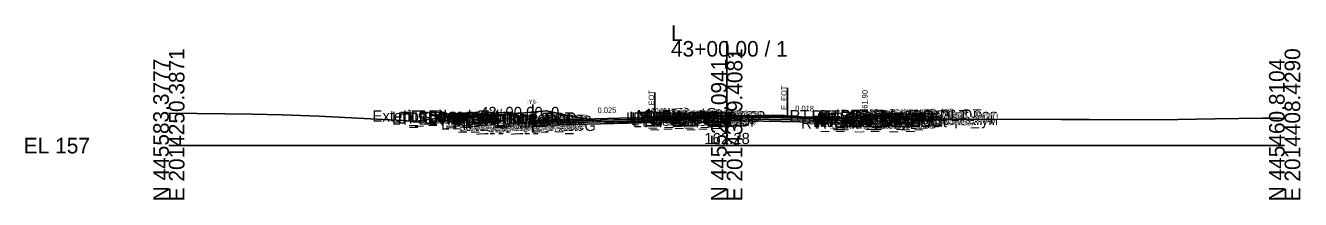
# Model space of a CAD drawing. Extents: x -26 to 4203, y -10 to 9526.
# Drawn here: x 2974.3 to 3202.8, y 2990.3 to 3021.6 of the extents above; entities that cross this region are included whole.
import ezdxf

# ---------------------------------------------------------------- set-up
doc = ezdxf.new("R2010")
doc.units = 0
for name, color, linetype in [('Default', 7, 'Continuous'), ('Exist CMT Pavement', 7, 'Continuous'), ('Exist Cross Section Cell', 7, 'Continuous'), ('Exist XS Center Line Elevation Label', 7, 'Continuous'), ('Exist XS Ground Line', 7, 'Continuous'), ('Prop CMT Conc Surface', 7, 'Continuous'), ('Prop CMT Concrete Structures', 7, 'Continuous'), ('Prop CMT Pvmt Course 1', 7, 'Continuous'), ('Prop CMT Pvmt Course 1 CG', 7, 'Continuous'), ('Prop CMT Pvmt Course 1 Wedge', 7, 'Continuous'), ('Prop CMT Pvmt Course 2', 7, 'Continuous'), ('Prop CMT Pvmt Course 2 Wedge', 7, 'Continuous'), ('Prop CMT Pvmt Course 3', 7, 'Continuous'), ('Prop CMT Pvmt Surface', 7, 'Continuous'), ('Prop CMT Pvmt Wedge Surface 1', 7, 'Continuous'), ('Prop CMT Pvmt Wedge Surface 2', 7, 'Continuous'), ('Prop CMT Pvmt Wedge Surface 3', 7, 'Continuous'), ('Prop CMT Shear Line', 7, 'Continuous'), ('Prop CMT Shear Line Text', 7, 'Continuous'), ('Prop CMT Slope Grass', 7, 'Continuous'), ('Prop CMT Subgrade Earthwork', 7, 'Continuous'), ('Prop XS Hydro Elevations', 7, 'Continuous'), ('Prop XS Label Text', 7, 'Continuous'), ('Prop XS SE Text', 7, 'Continuous'), ('Prop XS Side Slope Text', 7, 'Continuous'), ('Scratch_Level_0', 7, 'Continuous')]:
    doc.layers.add(name, color=color, linetype=linetype)

msp = doc.modelspace()

# ---------------------------------------------------------------- linework, layer by layer
at = {"layer": 'Exist CMT Pavement'}
for p, q in [((3097.81, 3005.2), (3099.49, 3005.27)), ((3099.49, 3005.27), (3100, 3005.28)), ((3087.09, 3004.57), (3088.54, 3004.67)), ((3088.54, 3004.67), (3090.65, 3004.8)), ((3090.65, 3004.8), (3092, 3004.89)), ((3092, 3004.89), (3095.19, 3005.08)), ((3095.19, 3005.08), (3096.95, 3005.16)), ((3096.95, 3005.16), (3097.81, 3005.2))]:
    msp.add_line(p, q, dxfattribs=at)
at = {"layer": 'Exist Cross Section Cell'}
for p, q in [((3100, 3000), (3100, 3018.79)), ((3000, 3000), (3100, 3000)), ((3100, 3000), (3200, 3000))]:
    msp.add_line(p, q, dxfattribs=at)
at = {"layer": 'Exist XS Ground Line'}
msp.add_lwpolyline([(3000, 3005.8), (3010.04, 3005.71), (3014.92, 3005.64), (3020.3, 3005.54), (3026.96, 3005.29), (3041.88, 3004.49), (3043.52, 3004.41), (3044.34, 3004.36), (3046.52, 3004.71), (3050.39, 3005.31), (3053.15, 3005.33), (3060.56, 3005.56), (3064.26, 3005.94), (3067.7, 3006.25), (3072.33, 3005.23), (3079.29, 3004.04), (3082.76, 3004.21), (3084.57, 3004.38), (3086.44, 3004.52), (3087.23, 3004.57), (3087.93, 3004.63), (3088.54, 3004.67), (3090.65, 3004.8), (3091.08, 3004.83), (3092.62, 3004.93), (3093.85, 3005.01), (3094.43, 3005.04), (3095.19, 3005.08), (3096.95, 3005.16), (3098.52, 3005.23), (3099.49, 3005.27), (3100.16, 3005.28), (3102.93, 3005.33), (3103.35, 3005.33), (3105.07, 3005.37), (3106.49, 3005.38), (3107.33, 3005.38), (3109.55, 3005.4), (3110.27, 3005.41), (3110.89, 3005.37), (3111.64, 3005.31), (3116.75, 3004.95), (3124.41, 3004.91), (3130.71, 3004.88), (3140.26, 3004.68), (3147.6, 3004.75), (3159.94, 3004.72), (3164.94, 3004.68), (3173.53, 3004.63), (3180.85, 3004.69), (3187.55, 3004.79), (3195.95, 3004.94), (3197.78, 3004.92), (3198.42, 3004.91), (3199, 3004.91), (3200, 3004.9)], dxfattribs=at)
at = {"layer": 'Prop CMT Conc Surface'}
for points in [[(3124.75, 3004.9), (3124.75, 3005.4), (3125.25, 3005.4)], [(3129.25, 3005.49), (3134.25, 3005.59)], [(3122.75, 3005.01), (3124.75, 3004.9)]]:
    msp.add_lwpolyline(points, dxfattribs=at)
at = {"layer": 'Prop CMT Concrete Structures'}
for points in [[(3096, 3005.48), (3095.99, 3005.65), (3095.24, 3005.9), (3094, 3005.92), (3092.76, 3005.63), (3092.01, 3005.38), (3092, 3005.21)], [(3092, 3005.21), (3096, 3005.48)], [(3122.75, 3005.01), (3124.75, 3004.9), (3124.75, 3005.4), (3125.25, 3005.4)], [(3125.25, 3005.4), (3125.25, 3004.39), (3122.75, 3004.43)], [(3134.25, 3005.59), (3129.25, 3005.49)], [(3129.25, 3005.49), (3129.25, 3005.16)], [(3129.25, 3005.16), (3134.25, 3005.26)], [(3134.25, 3005.26), (3134.25, 3005.59)], [(3122.75, 3004.43), (3122.75, 3005.01)]]:
    msp.add_lwpolyline(points, dxfattribs=at)
at = {"layer": 'Prop CMT Pvmt Course 1'}
for points in [[(3092, 3005.21), (3065.25, 3004.54)], [(3092, 3005.21), (3096, 3005.48)], [(3096, 3005.23), (3092, 3004.96)], [(3092, 3004.96), (3092, 3005.21)], [(3092, 3004.96), (3092, 3005.21)], [(3096, 3005.48), (3096, 3005.23)], [(3096, 3005.48), (3122.75, 3005.01)], [(3096, 3005.23), (3096, 3005.48)], [(3096, 3005.36), (3096, 3005.23), (3096, 3005.23)], [(3065.25, 3004.29), (3087.07, 3004.84)], [(3065.25, 3004.54), (3065.25, 3004.29)], [(3087.07, 3004.96), (3092, 3005.09)], [(3087.07, 3004.84), (3087.07, 3004.96)], [(3092, 3005.09), (3092, 3004.96), (3092, 3004.96)], [(3122.75, 3004.76), (3110.89, 3004.97)], [(3122.75, 3005.01), (3122.75, 3004.76)]]:
    msp.add_lwpolyline(points, dxfattribs=at)
at = {"layer": 'Prop CMT Pvmt Course 1 CG'}
for points in [[(3065.25, 3003.63), (3065.25, 3003.96)], [(3122.75, 3004.43), (3125.75, 3004.38), (3126.09, 3004.04)], [(3122.75, 3004.1), (3122.75, 3004.43)], [(3126.09, 3004.04), (3122.75, 3004.1)]]:
    msp.add_lwpolyline(points, dxfattribs=at)
at = {"layer": 'Prop CMT Pvmt Course 1 Wedge'}
for points in [[(3096, 3005.23), (3096, 3005.36)], [(3096, 3005.36), (3096.95, 3005.34), (3098.52, 3005.31), (3099.49, 3005.3), (3100, 3005.29)], [(3100.3, 3005.28), (3100.16, 3005.28), (3099.68, 3005.27), (3099.49, 3005.27), (3098.52, 3005.23), (3097.81, 3005.2), (3096.95, 3005.22), (3096, 3005.23)], [(3087.07, 3004.96), (3087.23, 3004.97), (3087.93, 3004.99), (3088.54, 3005), (3090.52, 3005.05), (3090.65, 3005.05), (3091.08, 3005.06), (3092, 3005.09)], [(3092, 3004.96), (3091.08, 3004.94), (3090.65, 3004.93), (3090.52, 3004.93), (3088.54, 3004.88), (3087.93, 3004.86), (3087.23, 3004.84), (3087.07, 3004.84)], [(3087.07, 3004.84), (3087.07, 3004.96)], [(3092, 3005.09), (3092, 3004.96)]]:
    msp.add_lwpolyline(points, dxfattribs=at)
at = {"layer": 'Prop CMT Pvmt Course 2'}
for points in [[(3092, 3004.96), (3096, 3005.23)], [(3096, 3005.23), (3096, 3004.9)], [(3087.07, 3004.84), (3065.25, 3004.29)], [(3065.25, 3003.96), (3087.07, 3004.51)], [(3065.25, 3004.29), (3065.25, 3003.96)], [(3087.07, 3004.51), (3087.07, 3004.84)], [(3092, 3004.63), (3092, 3004.96)], [(3100, 3005.16), (3122.75, 3004.76)], [(3122.75, 3004.43), (3100, 3004.83)], [(3122.75, 3004.76), (3122.75, 3004.43)]]:
    msp.add_lwpolyline(points, dxfattribs=at)
at = {"layer": 'Prop CMT Pvmt Course 2 Wedge'}
for points in [[(3096, 3005.23), (3096.95, 3005.22), (3097.81, 3005.2)], [(3096, 3005.12), (3096, 3005.23)], [(3087.07, 3004.84), (3087.23, 3004.84), (3087.93, 3004.86), (3088.54, 3004.88), (3090.52, 3004.93), (3090.65, 3004.93), (3091.08, 3004.94), (3092, 3004.96)], [(3092, 3004.89), (3091.08, 3004.83), (3090.65, 3004.8), (3090.52, 3004.79), (3088.54, 3004.67), (3087.93, 3004.63), (3087.23, 3004.57), (3087.07, 3004.56)], [(3087.07, 3004.56), (3087.07, 3004.84)], [(3092, 3004.96), (3092, 3004.89)], [(3097.81, 3005.2), (3096.95, 3005.16), (3096, 3005.12)]]:
    msp.add_lwpolyline(points, dxfattribs=at)
at = {"layer": 'Prop CMT Pvmt Course 3'}
for points in [[(3087.07, 3004.51), (3065.25, 3003.96)], [(3065.25, 3003.63), (3087.07, 3004.17)], [(3065.25, 3003.96), (3065.25, 3003.63)], [(3087.07, 3004.17), (3087.07, 3004.51)], [(3100, 3004.83), (3122.75, 3004.43)], [(3122.75, 3004.1), (3100, 3004.5)], [(3122.75, 3004.43), (3122.75, 3004.1)]]:
    msp.add_lwpolyline(points, dxfattribs=at)
at = {"layer": 'Prop CMT Pvmt Surface'}
for points in [[(3092, 3005.21), (3065.25, 3004.54)], [(3092, 3005.21), (3096, 3005.48)], [(3096, 3005.48), (3122.75, 3005.01)]]:
    msp.add_lwpolyline(points, dxfattribs=at)
at = {"layer": 'Prop CMT Pvmt Wedge Surface 1'}
for points in [[(3092, 3005.21), (3092, 3004.96), (3092, 3004.96), (3092, 3005.09)], [(3096, 3005.48), (3096, 3005.23), (3096, 3005.23), (3096, 3005.36)], [(3087.07, 3004.84), (3065.25, 3004.29)], [(3065.25, 3004.29), (3065.25, 3004.54)], [(3092, 3005.09), (3087.07, 3004.96)], [(3087.07, 3004.96), (3087.07, 3004.84)], [(3122.75, 3004.76), (3122.75, 3005.01)]]:
    msp.add_lwpolyline(points, dxfattribs=at)
at = {"layer": 'Prop CMT Pvmt Wedge Surface 2'}
for points in [[(3092, 3005.21), (3092, 3004.96)], [(3096, 3005.48), (3096, 3005.23)], [(3096, 3005.23), (3100, 3005.16)], [(3092, 3004.96), (3065.25, 3004.29)], [(3065.25, 3004.29), (3065.25, 3004.54)], [(3122.75, 3004.76), (3122.75, 3005.01)]]:
    msp.add_lwpolyline(points, dxfattribs=at)
at = {"layer": 'Prop CMT Pvmt Wedge Surface 3'}
for points in [[(3092, 3005.21), (3092, 3004.63)], [(3096, 3005.48), (3096, 3004.9)], [(3092, 3004.63), (3065.25, 3003.96)], [(3065.25, 3003.96), (3065.25, 3004.54)], [(3096, 3004.9), (3092, 3004.63)], [(3096, 3004.9), (3100, 3004.83)], [(3122.75, 3004.43), (3122.75, 3005.01)]]:
    msp.add_lwpolyline(points, dxfattribs=at)
at = {"layer": 'Prop CMT Shear Line'}
msp.add_line((3065.25, 3002.37), (3065.25, 3007.38), dxfattribs=at)
at = {"layer": 'Prop CMT Slope Grass'}
for points in [[(3125.25, 3005.4), (3134.25, 3005.58)], [(3134.25, 3005.58), (3134.75, 3005.59), (3137.3, 3004.74)]]:
    msp.add_lwpolyline(points, dxfattribs=at)
at = {"layer": 'Prop CMT Subgrade Earthwork'}
msp.add_line((3065.25, 3003.63), (3065.25, 3006.03), dxfattribs=at)
for points in [[(3100, 3004.5), (3100, 3005.28)], [(3122.75, 3004.1), (3126.09, 3004.04), (3127.49, 3005.44)], [(3087.07, 3004.17), (3065.25, 3003.63)], [(3087.07, 3004.17), (3087.09, 3004.57)], [(3100, 3004.5), (3122.75, 3004.1)]]:
    msp.add_lwpolyline(points, dxfattribs=at)
at = {"layer": 'Prop XS Label Text'}
for p, q in [((3110.87, 3010.38), (3110.87, 3005.38)), ((3087.09, 3009.57), (3087.09, 3004.57))]:
    msp.add_line(p, q, dxfattribs=at)

# ---------------------------------------------------------------- texts
at = {"layer": 'Default'}
msp.add_text('-', height=0.0001, dxfattribs=at).set_placement((3000, 3000))
at = {"layer": 'Exist Cross Section Cell'}
for s, p in [('L', (3090, 3018.79)), ('43+00.00 / 1', (3090, 3015.99)), ('EL 157', (2974, 2998.6))]:
    msp.add_text(s, height=2.8, dxfattribs=at).set_placement(p)
for s, p in [('E 2014250.3871', (3002.8, 2990)), ('E 2014329.4081', (3102.8, 2990)), ('E 2014408.4290', (3202.8, 2990)), ('N 445583.3777', (3000, 2990)), ('N 445522.0941', (3100, 2990)), ('N 445460.8104', (3200, 2990))]:
    msp.add_text(s, height=2.8, rotation=90, dxfattribs=at).set_placement(p)
at = {"layer": 'Exist XS Center Line Elevation Label'}
msp.add_text('162.28', height=2, dxfattribs=at).set_placement((3095.96, 3000.28))
at = {"layer": 'Prop CMT Shear Line Text'}
msp.add_text('-Y6-', height=0.75, dxfattribs=at).set_placement((3064.16, 3007.5))
at = {"layer": 'Prop XS Hydro Elevations'}
msp.add_text('161.90', height=1, rotation=90, dxfattribs=at).set_placement((3125.25, 3005.9))
at = {"layer": 'Prop XS Label Text'}
for p in [(3086.99, 3005.59), (3110.77, 3006.4)]:
    msp.add_text('E. EOT', height=1, rotation=90, dxfattribs=at).set_placement(p)
at = {"layer": 'Prop XS SE Text'}
for s, rotation, p in [('0.025', 1.4327, (3076.87, 3005.83)), ('0.018', 358.9936, (3112.27, 3006.2))]:
    msp.add_text(s, height=1, rotation=rotation, dxfattribs=at).set_placement(p)
at = {"layer": 'Prop XS Side Slope Text'}
msp.add_text('3:1', height=1, rotation=341.5651, dxfattribs=at).set_placement((3136.18, 3005.71))
at = {"layer": 'Scratch_Level_0'}
for s, p in [('Exterior Boundary', (3036.5, 3004.33)), ('LT_SDWK_Out_Top', (3039.99, 3004.1)), ('LT_SDWK_Out_Bot', (3040.02, 3003.77)), ('LT_Sub_Trench_Out_DLT', (3041.06, 3003.96)), ('LT_Slope_Cut', (3042, 3004.33)), ('LT_Slope_Fill', (3042.88, 3004.33)), ('LT_CSLP_Pnt', (3043.42, 3004.1)), ('LT_SDWK_In_Top', (3046.61, 3004)), ('LT_SDWK_In_Bot', (3046.64, 3003.67)), ('LT_CG_Top_Face', (3050.51, 3003.91)), ('LT_CG_Top_BOC', (3051.03, 3003.91)), ('LT_CG_Top_Gut', (3051.49, 3003.41)), ('LT_PV2_OEEOP', (3054.56, 3003.29)), ('LT_PV1_OEEOP', (3055.12, 3003.42)), ('LT_PV2_OEOT', (3055.42, 3003.29)), ('43+00.00_0', (3055.79, 3004.96)), ('LT_PV1_OEOT', (3055.99, 3003.54)), ('LT_PV2_IEEOP', (3081.95, 3003.96)), ('LT_PV1_IEEOP', (3082.52, 3004.09)), ('LT_PV2_PGL1', (3082.88, 3003.96)), ('LT_PV3_PGL1', (3082.88, 3003.63)), ('LT_PV2_PGL', (3083.21, 3003.96)), ('LT_PV4_PGL', (3083.21, 3003.3)), ('LT_PV1_PGL', (3083.78, 3004.21)), ('MI_Face In', (3083.9, 3004.38)), ('RT_Sub_OEEOP', (3085.17, 3003.43)), ('RT_PV2_OEEOP', (3085.26, 3004.09)), ('RT_PV3_OEEOP', (3085.26, 3003.76)), ('MI_Top In', (3085.61, 3004.63)), ('RT_PV1_OEEOP', (3085.83, 3004.22)), ('RT_PV2_IEEOP', (3085.91, 3004.09)), ('MI_Face Out', (3086.26, 3004.51)), ('MI_Top Out', (3086.47, 3004.76)), ('RT_PV1_IEEOP', (3086.47, 3004.22)), ('RT_PV2_PGL1', (3086.83, 3004.23)), ('RT_PV3_PGL1', (3086.83, 3003.9)), ('MI_Crown', (3087.07, 3004.78)), ('RT_PV2_PGL', (3087.17, 3004.09)), ('RT_PV4_PGL', (3087.17, 3003.57)), ('MI_Bot Out', (3087.26, 3004.34)), ('RT_PV1_PGL', (3087.73, 3004.34)), ('RT_Sub_Trench_Out_DLT', (3111.26, 3004.39)), ('RT_CG_Top_Face', (3115.21, 3004.34)), ('RT_CG1_Shelf_Out', (3115.5, 3003.32)), ('RT_CG_Bot_IE', (3115.87, 3003.37)), ('RT_PV2_OEOT', (3116.13, 3003.71)), ('RT_PV3_OEOT', (3116.13, 3003.37)), ('RT_CG_Top_Gut', (3116.19, 3003.84)), ('RT_PV1_OEOT', (3116.69, 3003.96)), ('RT_CG_Top_BOC', (3116.74, 3004.34)), ('RT_CG_Bot_BOC', (3116.77, 3003.33)), ('RT_SDWK_In_Top', (3120.31, 3004.43)), ('RT_SDWK_In_Bot', (3120.34, 3004.1)), ('RT_SDWK_Out_Top', (3123.69, 3004.53)), ('RT_SDWK_Out_Bot', (3123.72, 3004.2)), ('Exterior Boundary', (3125.52, 3003.69)), ('RT_Shld_O', (3130.04, 3004.52)), ('CSLP_Pnt', (3130.87, 3004.53)), ('RT_Slope_Fill', (3131.85, 3003.69)), ('LT_CG1_Shelf_Out', (3048.8, 3002.88)), ('LT_CG_Bot_BOC', (3051.07, 3002.9)), ('LT_Sub_OEOP', (3052.02, 3002.54)), ('LT_Sub_OEOT_CG', (3052.62, 3002.63)), ('LT_Sub_OEEOP', (3054.46, 3002.63)), ('LT_PV3_OEEOP', (3054.56, 3002.96)), ('LT_CG_Bot_IE', (3055.16, 3002.96)), ('LT_Sub_OEOT', (3055.33, 3002.63)), ('LT_PV3_OEOT', (3055.42, 3002.96)), ('RT_Sub_OEOT_CG', (3113.32, 3003.04)), ('RT_Sub_OEOT', (3116.03, 3003.04)), ('RT_Sub_OEOP', (3119.4, 3002.98))]:
    msp.add_text(s, height=2, dxfattribs=at).set_placement(p)

doc.saveas('drawing.dxf')
